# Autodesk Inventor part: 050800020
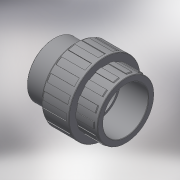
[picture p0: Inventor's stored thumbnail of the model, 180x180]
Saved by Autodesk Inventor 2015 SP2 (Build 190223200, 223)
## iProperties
Created: 2017-10
Part Number: 050800020
Material: Generic
Description: PLASSON UNION+O RING-CEM PVC 20
Document SubType Name: Modeling
Designer: Кирилл
Density: 1 g/cm^3
Appearance: Default
Author: Кирилл
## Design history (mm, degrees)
derived "050800.ipt"
feature "Solid1::050800.ipt"
tag "TaggingFeature1"
body "Solid1"
other parameters: "d0" = 45, "d5" = 24, "d6" = 25, "d7" = 25.6, "d8" = 42, "d9" = 16, "d10" = 16, "d11" = 18, "d12" = 19, "d14" = 12, "d15" = 12, "d16" = 11.7, "d17" = 1.6, "d19" = 41.16, "d20" = 1.6, "d21" = 1.26, "d25" = 4.2, "d26" = 2.1, "d27" = 17.46, "d28" = 0, "d32" = 4.2, "d33" = 2.1, "d35" = 0, "d39" = 0.2, "d45" = 0.3, "d49" = 360 deg, "d51" = 0.42, "d55" = 360 deg, "E_" = 42, "H_" = 45, "l_" = 16, "l_1" = 16, "Z_" = 13, "d13" = 13, "d24" = 19.4, "d40" = 0.3, "d44" = 0.42
